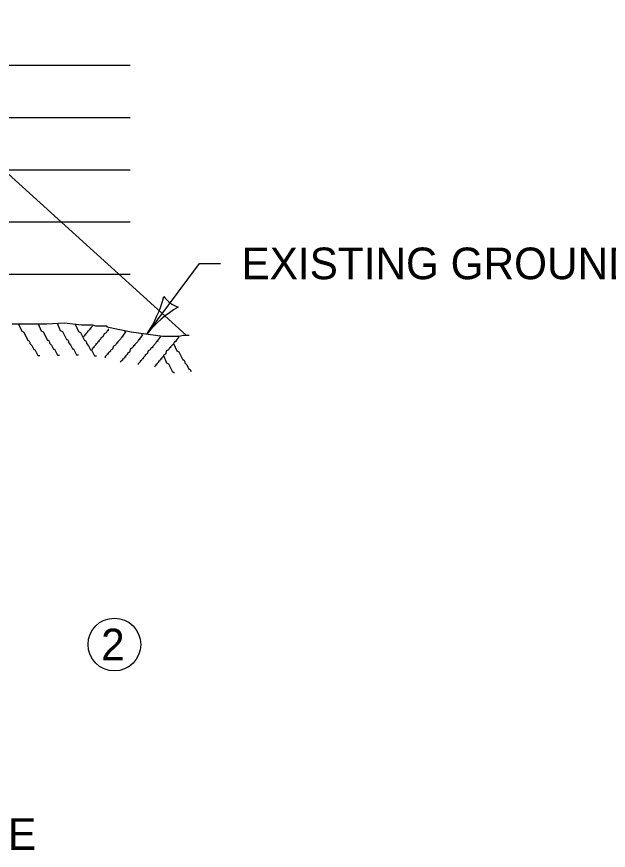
# Model space of a CAD drawing. Extents: x 49991.4 to 50021, y 49987.6 to 50011.4.
# Drawn here: x 50015.519 to 50016.641, y 50004.847 to 50006.427 of the extents above; entities that cross this region are included whole.
import ezdxf

# ---------------------------------------------------------------- set-up
doc = ezdxf.new("R2010")
doc.units = 0
for name, color, linetype in [('Level 1', 7, 'Continuous'), ('Level 2', 7, 'Continuous'), ('Level 3', 7, 'Continuous')]:
    doc.layers.add(name, color=color, linetype=linetype)

msp = doc.modelspace()

# ---------------------------------------------------------------- linework, layer by layer
at = {"layer": 'Level 1'}
for p, q in [((50015.8403, 50005.8238), (50013.8839, 50007.5958)), ((50015.7342, 50006.3346), (50013.9592, 50006.3346)), ((50015.7342, 50006.2356), (50013.9592, 50006.2356)), ((50015.7342, 50006.1366), (50013.9592, 50006.1366)), ((50015.7342, 50006.0376), (50014.2021, 50006.0376)), ((50015.7342, 50005.9386), (50014.3195, 50005.9386))]:
    msp.add_line(p, q, dxfattribs=at)
for points in [[(50015.5107, 50005.845), (50015.5704, 50005.845), (50015.5762, 50005.845), (50015.6091, 50005.8469), (50015.6418, 50005.8431), (50015.663, 50005.8431), (50015.6688, 50005.8412), (50015.6823, 50005.8412), (50015.69, 50005.8412), (50015.69, 50005.8392), (50015.7363, 50005.8296), (50015.796, 50005.8219), (50015.8269, 50005.8219), (50015.8346, 50005.8238), (50015.8461, 50005.8238)], [(50015.5227, 50005.8446), (50015.5285, 50005.8311), (50015.5323, 50005.8291), (50015.54, 50005.8137), (50015.542, 50005.8137), (50015.5439, 50005.8098), (50015.5439, 50005.8079), (50015.5478, 50005.8041), (50015.5516, 50005.7963), (50015.5536, 50005.7963), (50015.5593, 50005.7848), (50015.5632, 50005.7848)], [(50015.5598, 50005.845), (50015.5656, 50005.8315), (50015.5695, 50005.8296), (50015.5772, 50005.8142), (50015.5791, 50005.8142), (50015.581, 50005.8103), (50015.581, 50005.8084), (50015.5849, 50005.8046), (50015.5888, 50005.7968), (50015.5907, 50005.7968), (50015.5965, 50005.7853), (50015.6003, 50005.7853)], [(50015.596, 50005.846), (50015.6017, 50005.8325), (50015.6056, 50005.8306), (50015.6133, 50005.8152), (50015.6152, 50005.8152), (50015.6172, 50005.8113), (50015.6172, 50005.8094), (50015.621, 50005.8055), (50015.6249, 50005.7978), (50015.6269, 50005.7978), (50015.6326, 50005.7862), (50015.6365, 50005.7862)], [(50015.6302, 50005.8441), (50015.636, 50005.8306), (50015.6399, 50005.8286), (50015.6476, 50005.8132), (50015.6495, 50005.8132), (50015.6514, 50005.8094), (50015.6514, 50005.8074), (50015.6553, 50005.8036), (50015.6591, 50005.7959), (50015.661, 50005.7959), (50015.6668, 50005.7843), (50015.6707, 50005.7843)], [(50015.6626, 50005.8403), (50015.6591, 50005.8368), (50015.6591, 50005.8349), (50015.6572, 50005.8349), (50015.6553, 50005.8311), (50015.6533, 50005.8311), (50015.6533, 50005.8291), (50015.6494, 50005.8253), (50015.6494, 50005.8234), (50015.6476, 50005.8234), (50015.6456, 50005.8195)], [(50015.6939, 50005.8356), (50015.6924, 50005.834), (50015.6924, 50005.832), (50015.6904, 50005.832), (50015.6885, 50005.8282), (50015.6847, 50005.8262), (50015.6827, 50005.8205), (50015.6789, 50005.8185), (50015.6789, 50005.8166), (50015.675, 50005.8127), (50015.675, 50005.8108), (50015.6731, 50005.8108), (50015.6711, 50005.807), (50015.6692, 50005.807), (50015.6692, 50005.8051), (50015.6654, 50005.8012), (50015.6654, 50005.7993), (50015.6634, 50005.7993), (50015.6615, 50005.7954)], [(50015.7237, 50005.8315), (50015.7256, 50005.8296), (50015.7198, 50005.8219), (50015.7198, 50005.82), (50015.7179, 50005.82), (50015.716, 50005.8161), (50015.7102, 50005.8103), (50015.7102, 50005.8084), (50015.7082, 50005.8084), (50015.7064, 50005.8046), (50015.7025, 50005.8026), (50015.7005, 50005.7969), (50015.6967, 50005.7949), (50015.6967, 50005.793), (50015.6928, 50005.7891), (50015.6928, 50005.7872), (50015.6909, 50005.7872), (50015.689, 50005.7834), (50015.6871, 50005.7834), (50015.6871, 50005.7814), (50015.6865, 50005.7808)], [(50015.756, 50005.8262), (50015.7579, 50005.8243), (50015.7521, 50005.8166), (50015.7521, 50005.8147), (50015.7502, 50005.8147), (50015.7483, 50005.8108), (50015.7425, 50005.8051), (50015.7425, 50005.8031), (50015.7406, 50005.8031), (50015.7386, 50005.7993), (50015.7348, 50005.7974), (50015.7328, 50005.7915), (50015.729, 50005.7896), (50015.729, 50005.7877), (50015.7252, 50005.7838), (50015.7252, 50005.7819), (50015.7232, 50005.7819), (50015.7213, 50005.778), (50015.7194, 50005.778), (50015.7194, 50005.7761), (50015.7155, 50005.7722)], [(50015.7897, 50005.8229), (50015.7917, 50005.821), (50015.7859, 50005.8132), (50015.7859, 50005.8113), (50015.7839, 50005.8113), (50015.782, 50005.8074), (50015.7763, 50005.8017), (50015.7763, 50005.7997), (50015.7743, 50005.7997), (50015.7724, 50005.7959), (50015.7685, 50005.794), (50015.7666, 50005.7881), (50015.7627, 50005.7862), (50015.7627, 50005.7843), (50015.7589, 50005.7805), (50015.7589, 50005.7785), (50015.757, 50005.7785), (50015.755, 50005.7747), (50015.7531, 50005.7747), (50015.7531, 50005.7727), (50015.7492, 50005.7689), (50015.7492, 50005.7682)], [(50015.8244, 50005.8224), (50015.8264, 50005.8205), (50015.8206, 50005.8127), (50015.8206, 50005.8108), (50015.8186, 50005.8108), (50015.8167, 50005.807), (50015.8109, 50005.8012), (50015.8109, 50005.7993), (50015.809, 50005.7993), (50015.8071, 50005.7954), (50015.8032, 50005.7935), (50015.8013, 50005.7877), (50015.7974, 50005.7858), (50015.7974, 50005.7838), (50015.7936, 50005.78), (50015.7936, 50005.778), (50015.7917, 50005.778), (50015.7897, 50005.7742), (50015.7878, 50005.7742), (50015.7878, 50005.7722), (50015.7839, 50005.7684), (50015.7839, 50005.7665), (50015.782, 50005.7665), (50015.7801, 50005.7626)], [(50015.8167, 50005.8074), (50015.8225, 50005.7939), (50015.8264, 50005.792), (50015.8341, 50005.7766), (50015.836, 50005.7766), (50015.8379, 50005.7727), (50015.8379, 50005.7708), (50015.8418, 50005.767), (50015.8456, 50005.7592), (50015.8476, 50005.7592), (50015.8497, 50005.7549)], [(50015.7974, 50005.7848), (50015.8032, 50005.7713), (50015.8071, 50005.7693), (50015.8148, 50005.7539), (50015.8167, 50005.7539), (50015.8178, 50005.7517)]]:
    msp.add_lwpolyline(points, dxfattribs=at)
at = {"layer": 'Level 2'}
msp.add_circle((50015.7043, 50005.2369), 0.05, dxfattribs=at)
at = {"layer": 'Level 3'}
for p, q in [((50015.7662, 50005.8258), (50015.8658, 50005.9596)), ((50015.8658, 50005.9596), (50015.9054, 50005.9596))]:
    msp.add_line(p, q, dxfattribs=at)
for centre, radius, start, end in [((50015.5726, 50005.9554), 0.233, 326.1809, 345.4308), ((50015.8427, 50005.9286), 0.0548, 215.4925, 251.2148), ((50015.9389, 50005.6858), 0.2223, 120.8096, 140.9932)]:
    msp.add_arc(centre, radius, start, end, dxfattribs=at)

# ---------------------------------------------------------------- texts
at = {"layer": 'Level 2'}
for s, p in [('EXISTING GROUND', (50015.9454, 50005.9296)), ('2', (50015.6792, 50005.2069)), ('STABILIZATION GEOTEXTILE', (50014.437, 50004.8475))]:
    msp.add_text(s, height=0.06, dxfattribs=at).set_placement(p)

doc.saveas('drawing.dxf')
